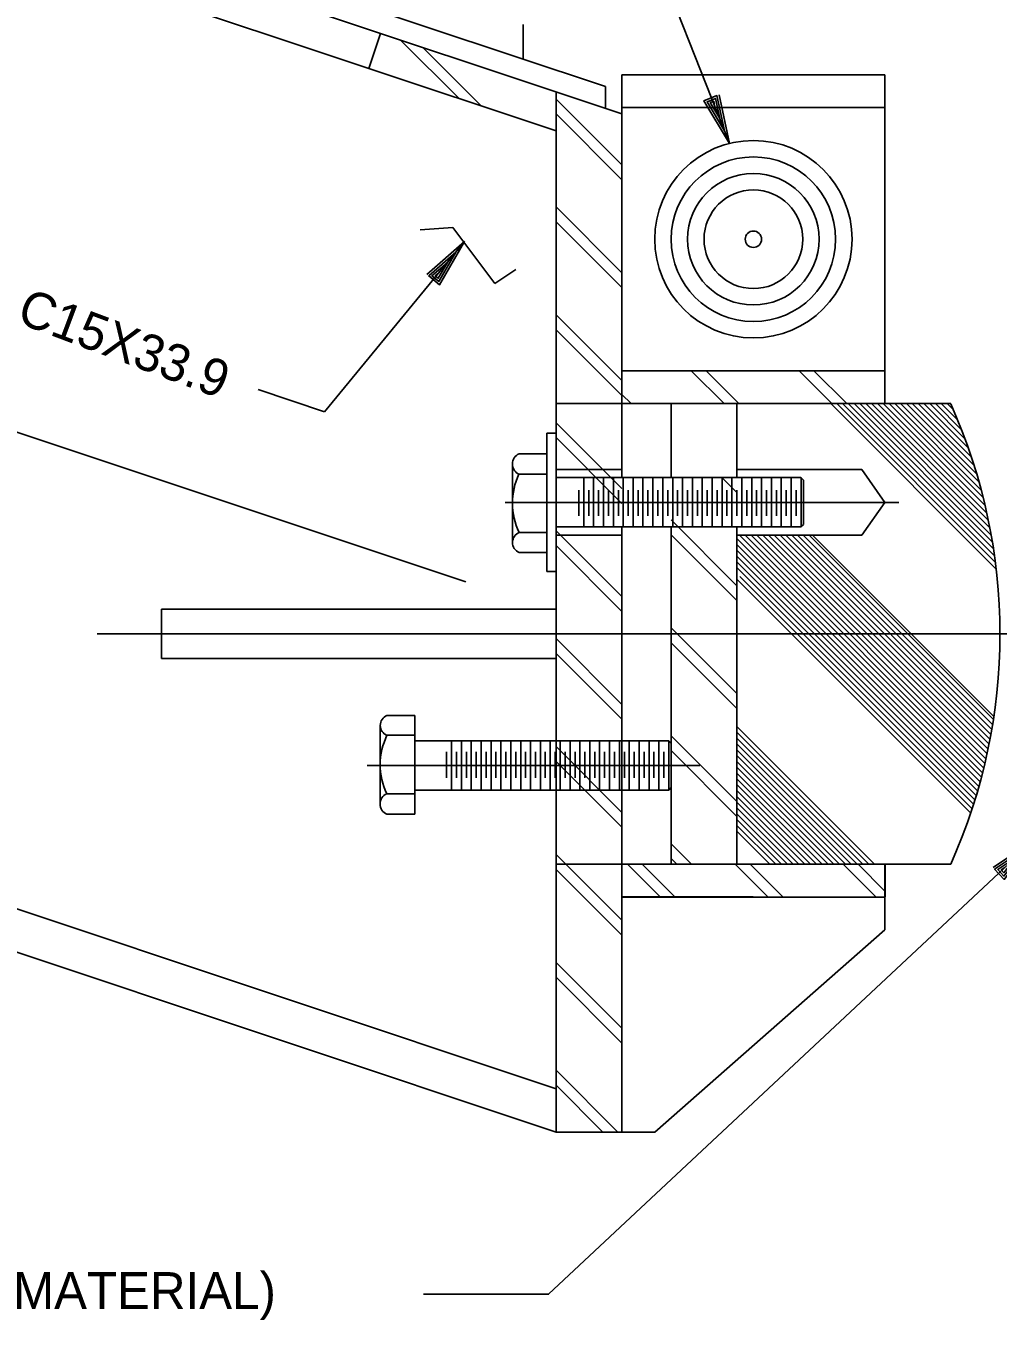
# Model space of a CAD drawing. Extents: x 0.1 to 13.5, y 0.1 to 9.5.
# Drawn here: x 1.9 to 3.132, y 4.936 to 6.576 of the extents above; entities that cross this region are included whole.
import ezdxf

# ---------------------------------------------------------------- set-up
doc = ezdxf.new("R2010")
doc.units = 0
for name, color, linetype in [('Level 1', 7, 'Continuous'), ('Level 13', 7, 'Continuous'), ('Level 25', 7, 'Continuous'), ('Level 3', 7, 'Continuous'), ('Level 44', 7, 'Continuous'), ('Level 50', 7, 'Continuous')]:
    doc.layers.add(name, color=color, linetype=linetype)

msp = doc.modelspace()

# ---------------------------------------------------------------- linework, layer by layer
at = {"layer": 'Level 13'}
for p, q in [((2.5606, 6.0598), (2.5606, 5.8848)), ((2.5606, 6.0598), (2.5722, 6.0598)), ((2.5722, 6.0598), (2.5722, 5.8848)), ((2.5253, 6.0339), (2.5606, 6.0339)), ((2.5606, 6.0339), (2.5606, 5.9089)), ((2.5169, 6.0211), (2.5169, 5.9214)), ((2.525, 6.0081), (2.5606, 6.0081)), ((2.8014, 6.0036), (2.5722, 6.0036)), ((2.6073, 6.0036), (2.6073, 5.9411)), ((2.6198, 6.0036), (2.6198, 5.9411)), ((2.6324, 6.0036), (2.6324, 5.9411)), ((2.6448, 6.0036), (2.6448, 5.9411)), ((2.6574, 6.0036), (2.6574, 5.9411)), ((2.6699, 6.0036), (2.6699, 5.9411)), ((2.6823, 6.0036), (2.6823, 5.9411)), ((2.695, 6.0036), (2.695, 5.9411)), ((2.7074, 6.0036), (2.7074, 5.9411)), ((2.72, 6.0036), (2.72, 5.9411)), ((2.7325, 6.0036), (2.7325, 5.9411)), ((2.7449, 6.0036), (2.7449, 5.9411)), ((2.7575, 6.0036), (2.7575, 5.9411)), ((2.77, 6.0036), (2.77, 5.9411)), ((2.7825, 6.0036), (2.7825, 5.9411)), ((2.795, 6.0036), (2.795, 5.9411)), ((2.8014, 6.0036), (2.8825, 6.0036)), ((2.8075, 6.0036), (2.8075, 5.9411)), ((2.8201, 6.0036), (2.8201, 5.9411)), ((2.8325, 6.0036), (2.8325, 5.9411)), ((2.8451, 6.0036), (2.8451, 5.9411)), ((2.8576, 6.0036), (2.8576, 5.9411)), ((2.87, 6.0036), (2.87, 5.9411)), ((2.8825, 6.0036), (2.8856, 6.0002)), ((2.8826, 6.0036), (2.8826, 5.9411)), ((2.8856, 6.0002), (2.8856, 5.9442)), ((2.601, 5.9879), (2.601, 5.9551)), ((2.6136, 5.9879), (2.6136, 5.9551)), ((2.6261, 5.9879), (2.6261, 5.9551)), ((2.6386, 5.9879), (2.6386, 5.9551)), ((2.6511, 5.9879), (2.6511, 5.9551)), ((2.6636, 5.9879), (2.6636, 5.9551)), ((2.6761, 5.9879), (2.6761, 5.9551)), ((2.6886, 5.9879), (2.6886, 5.9551)), ((2.6886, 5.9879), (2.6886, 5.9551)), ((2.6886, 5.9879), (2.6886, 5.9551)), ((2.6886, 5.9879), (2.6886, 5.9551)), ((2.7012, 5.9879), (2.7012, 5.9551)), ((2.7137, 5.9879), (2.7137, 5.9551)), ((2.7261, 5.9879), (2.7261, 5.9551)), ((2.7387, 5.9879), (2.7387, 5.9551)), ((2.7512, 5.9879), (2.7512, 5.9551)), ((2.7512, 5.9879), (2.7512, 5.9551)), ((2.7512, 5.9879), (2.7512, 5.9551)), ((2.7638, 5.9879), (2.7638, 5.9551)), ((2.7763, 5.9879), (2.7763, 5.9551)), ((2.7887, 5.9879), (2.7887, 5.9551)), ((2.8013, 5.9879), (2.8013, 5.9551)), ((2.8138, 5.9879), (2.8138, 5.9551)), ((2.8138, 5.9879), (2.8138, 5.9551)), ((2.8263, 5.9879), (2.8263, 5.9551)), ((2.8388, 5.9879), (2.8388, 5.9551)), ((2.8513, 5.9879), (2.8513, 5.9551)), ((2.8638, 5.9879), (2.8638, 5.9551)), ((2.8763, 5.9879), (2.8763, 5.9551)), ((2.8014, 5.9411), (2.5722, 5.9411)), ((2.8014, 5.9411), (2.8822, 5.9411)), ((2.8822, 5.9411), (2.8856, 5.9442)), ((2.5252, 5.9341), (2.5606, 5.9341)), ((2.5253, 5.9089), (2.5606, 5.9089)), ((2.5606, 5.8848), (2.5722, 5.8848)), ((2.3493, 5.5902), (2.3493, 5.6899)), ((2.3577, 5.7024), (2.393, 5.7024)), ((2.393, 5.5774), (2.393, 5.7024)), ((2.3576, 5.6772), (2.393, 5.6772)), ((2.6338, 5.6702), (2.393, 5.6702)), ((2.4334, 5.6234), (2.4334, 5.6561)), ((2.4397, 5.6077), (2.4397, 5.6702)), ((2.446, 5.6234), (2.446, 5.6561)), ((2.4522, 5.6077), (2.4522, 5.6702)), ((2.4585, 5.6234), (2.4585, 5.6561)), ((2.4648, 5.6077), (2.4648, 5.6702)), ((2.471, 5.6234), (2.471, 5.6561)), ((2.4772, 5.6077), (2.4772, 5.6702)), ((2.4835, 5.6234), (2.4835, 5.6561)), ((2.4898, 5.6077), (2.4898, 5.6702)), ((2.496, 5.6234), (2.496, 5.6561)), ((2.5023, 5.6077), (2.5023, 5.6702)), ((2.5085, 5.6234), (2.5085, 5.6561)), ((2.5147, 5.6077), (2.5147, 5.6702)), ((2.521, 5.6234), (2.521, 5.6561)), ((2.521, 5.6234), (2.521, 5.6561)), ((2.521, 5.6234), (2.521, 5.6561)), ((2.521, 5.6234), (2.521, 5.6561)), ((2.5274, 5.6077), (2.5274, 5.6702)), ((2.5336, 5.6234), (2.5336, 5.6561)), ((2.5398, 5.6077), (2.5398, 5.6702)), ((2.5461, 5.6234), (2.5461, 5.6561)), ((2.5524, 5.6077), (2.5524, 5.6702)), ((2.5585, 5.6234), (2.5585, 5.6561)), ((2.5649, 5.6077), (2.5649, 5.6702)), ((2.5711, 5.6234), (2.5711, 5.6561)), ((2.5773, 5.6077), (2.5773, 5.6702)), ((2.5836, 5.6234), (2.5836, 5.6561)), ((2.5836, 5.6234), (2.5836, 5.6561)), ((2.5836, 5.6234), (2.5836, 5.6561)), ((2.5899, 5.6077), (2.5899, 5.6702)), ((2.5962, 5.6234), (2.5962, 5.6561)), ((2.6024, 5.6077), (2.6024, 5.6702)), ((2.6087, 5.6234), (2.6087, 5.6561)), ((2.6149, 5.6077), (2.6149, 5.6702)), ((2.6211, 5.6234), (2.6211, 5.6561)), ((2.6274, 5.6077), (2.6274, 5.6702)), ((2.6337, 5.6234), (2.6337, 5.6561)), ((2.6338, 5.6702), (2.7146, 5.6702)), ((2.6399, 5.6077), (2.6399, 5.6702)), ((2.6462, 5.6234), (2.6462, 5.6561)), ((2.6462, 5.6234), (2.6462, 5.6561)), ((2.6525, 5.6077), (2.6525, 5.6702)), ((2.6587, 5.6234), (2.6587, 5.6561)), ((2.6649, 5.6077), (2.6649, 5.6702)), ((2.6712, 5.6234), (2.6712, 5.6561)), ((2.6775, 5.6077), (2.6775, 5.6702)), ((2.6837, 5.6234), (2.6837, 5.6561)), ((2.69, 5.6077), (2.69, 5.6702)), ((2.6962, 5.6234), (2.6962, 5.6561)), ((2.7024, 5.6077), (2.7024, 5.6702)), ((2.7087, 5.6234), (2.7087, 5.6561)), ((2.7146, 5.6702), (2.718, 5.6671)), ((2.715, 5.6077), (2.715, 5.6702)), ((2.718, 5.611), (2.718, 5.6671)), ((2.6338, 5.6077), (2.393, 5.6077)), ((2.6338, 5.6077), (2.7149, 5.6077)), ((2.7149, 5.6077), (2.718, 5.611)), ((2.3574, 5.6032), (2.393, 5.6032)), ((2.3577, 5.5774), (2.393, 5.5774))]:
    msp.add_line(p, q, dxfattribs=at)
for centre, radius, start, end in [((2.5309, 6.0209), 0.0141, 113.1675, 245.9991), ((2.6023, 5.9714), 0.0854, 154.5519, 205.884), ((2.5307, 5.9215), 0.0137, 112.375, 247.1995), ((2.3631, 5.6898), 0.0137, 112.8005, 247.625), ((2.4347, 5.6399), 0.0854, 154.116, 205.4481), ((2.3633, 5.5903), 0.0141, 114.0009, 246.8325)]:
    msp.add_arc(centre, radius, start, end, dxfattribs=at)
at = {"layer": 'Level 25'}
for p, q in [((2.4512, 7.2856), (2.7921, 6.4269)), ((1.3561, 6.9251), (2.6347, 6.4989)), ((1.3478, 6.9003), (2.6555, 6.4644)), ((1.333, 6.8559), (2.5722, 6.4428)), ((2.5305, 6.5336), (2.5305, 6.5775)), ((2.3499, 6.5663), (2.335, 6.5219)), ((2.9889, 6.514), (2.6555, 6.514)), ((2.6555, 6.0036), (2.6555, 6.514)), ((2.9889, 6.0973), (2.9889, 6.514)), ((2.5722, 5.1746), (2.5722, 6.4922)), ((2.6347, 6.4714), (2.6347, 6.4989)), ((2.9889, 6.4723), (2.6555, 6.4723)), ((2.3999, 6.3174), (2.4413, 6.3203)), ((2.4413, 6.3203), (2.4946, 6.2493)), ((1.1502, 6.3074), (2.4579, 5.8715)), ((2.2788, 6.0871), (2.4561, 6.3026)), ((2.4946, 6.2493), (2.5212, 6.2671)), ((2.9889, 6.139), (2.6555, 6.139)), ((2.1945, 6.1152), (2.2788, 6.0871)), ((2.6555, 6.0973), (2.5722, 6.0973)), ((3.0722, 6.0973), (2.6555, 6.0973)), ((2.718, 6.0036), (2.718, 6.0973)), ((2.8014, 6.0036), (2.8014, 6.0973)), ((2.6555, 6.014), (2.5722, 6.014)), ((2.9597, 6.014), (2.8014, 6.014)), ((2.9597, 6.014), (2.9889, 5.9723)), ((3.0067, 5.9723), (2.5078, 5.9723)), ((2.9597, 5.9306), (2.9889, 5.9723)), ((2.6555, 5.1746), (2.6555, 5.9411)), ((2.718, 5.514), (2.718, 5.9411)), ((2.8014, 5.514), (2.8014, 5.9411)), ((2.6555, 5.9306), (2.5722, 5.9306)), ((2.9597, 5.9306), (2.8014, 5.9306)), ((2.5722, 5.8369), (2.0722, 5.8369)), ((2.0722, 5.7744), (2.0722, 5.8369)), ((3.2313, 5.8056), (1.9905, 5.8056)), ((3.2313, 5.8056), (1.9905, 5.8056)), ((3.0381, 5.8056), (3.6139, 5.8056)), ((3.0381, 5.8056), (4.2789, 5.8056)), ((2.5722, 5.7744), (2.0722, 5.7744)), ((0.969, 5.7639), (2.5722, 5.2295)), ((0.9526, 5.7145), (2.5722, 5.1746)), ((2.7544, 5.639), (2.3328, 5.639)), ((2.6555, 5.514), (2.5722, 5.514)), ((3.0722, 5.514), (2.6555, 5.514)), ((2.9889, 5.4306), (2.9889, 5.514)), ((2.9889, 5.4306), (2.989, 5.514)), ((2.9889, 5.4723), (2.6555, 5.4723)), ((2.9889, 5.4723), (2.6556, 5.4729)), ((2.6972, 5.1745), (2.9889, 5.4306)), ((2.5722, 5.1746), (2.6555, 5.1746)), ((2.6972, 5.1745), (2.6555, 5.1746))]:
    msp.add_line(p, q, dxfattribs=at)
for radius in [0.125, 0.1042, 0.0833, 0.0625, 0.0104]:
    msp.add_circle((2.8222, 6.3056), radius, dxfattribs=at)
msp.add_arc((2.4229, 5.8056), 0.7118, 335.8105, 24.1895, dxfattribs=at)
at = {"layer": 'Level 3'}
for p, q in [((3.13, 5.8877), (2.9204, 6.0973)), ((3.1289, 5.8961), (2.9278, 6.0973)), ((3.1278, 5.9046), (2.9351, 6.0973)), ((3.1265, 5.9133), (2.9425, 6.0973)), ((3.1251, 5.922), (2.9499, 6.0973)), ((3.1236, 5.9309), (2.9572, 6.0973)), ((3.1219, 5.94), (2.9646, 6.0973)), ((3.1201, 5.9492), (2.9719, 6.0973)), ((3.1181, 5.9585), (2.9793, 6.0973)), ((3.1159, 5.9681), (2.9867, 6.0973)), ((3.1136, 5.9778), (2.9941, 6.0973)), ((3.111, 5.9877), (3.0014, 6.0973)), ((3.1083, 5.9978), (3.0088, 6.0973)), ((3.1053, 6.0082), (3.0162, 6.0973)), ((3.1021, 6.0188), (3.0235, 6.0973)), ((3.0985, 6.0296), (3.0309, 6.0973)), ((3.0947, 6.0408), (3.0382, 6.0973)), ((3.0906, 6.0523), (3.0456, 6.0973)), ((3.0861, 6.0642), (3.053, 6.0973)), ((3.0812, 6.0765), (3.0603, 6.0973)), ((3.0758, 6.0893), (3.0677, 6.0973)), ((3.1096, 5.6182), (2.8014, 5.9264)), ((3.108, 5.6124), (2.8014, 5.919)), ((3.1111, 5.624), (2.8045, 5.9306)), ((3.1127, 5.6298), (2.8119, 5.9306)), ((3.1141, 5.6357), (2.8192, 5.9306)), ((3.1156, 5.6417), (2.8266, 5.9306)), ((3.1169, 5.6476), (2.834, 5.9306)), ((3.1183, 5.6537), (2.8413, 5.9306)), ((3.1196, 5.6597), (2.8487, 5.9306)), ((3.1208, 5.6659), (2.8561, 5.9306)), ((3.1221, 5.672), (2.8634, 5.9306)), ((3.1232, 5.6782), (2.8708, 5.9306)), ((3.1243, 5.6845), (2.8781, 5.9306)), ((3.1254, 5.6908), (2.8855, 5.9306)), ((3.1264, 5.6971), (2.8929, 5.9306)), ((3.127, 5.7009), (2.8972, 5.9306)), ((3.1063, 5.6067), (2.8014, 5.9117)), ((3.1047, 5.601), (2.8014, 5.9043)), ((3.1029, 5.5954), (2.8014, 5.8969)), ((3.1012, 5.5898), (2.8014, 5.8896)), ((3.0976, 5.5787), (2.8014, 5.8748)), ((3.0994, 5.5842), (2.8051, 5.8785)), ((2.9757, 5.514), (2.8014, 5.6883)), ((2.9684, 5.514), (2.8014, 5.681)), ((2.961, 5.514), (2.8014, 5.6736)), ((2.9536, 5.514), (2.8014, 5.6662)), ((2.9463, 5.514), (2.8014, 5.6589)), ((2.9389, 5.514), (2.8014, 5.6515)), ((2.9315, 5.514), (2.8014, 5.6441)), ((2.9242, 5.514), (2.8014, 5.6368)), ((2.9168, 5.514), (2.8014, 5.6294)), ((2.9095, 5.514), (2.8014, 5.6221)), ((2.9021, 5.514), (2.8014, 5.6147)), ((2.8947, 5.514), (2.8014, 5.6073)), ((2.8874, 5.514), (2.8014, 5.5999)), ((2.88, 5.514), (2.8014, 5.5926)), ((2.8726, 5.514), (2.8014, 5.5852)), ((2.8653, 5.514), (2.8014, 5.5778)), ((2.8579, 5.514), (2.8014, 5.5705)), ((2.8505, 5.514), (2.8014, 5.5631)), ((2.8432, 5.514), (2.8014, 5.5558))]:
    msp.add_line(p, q, dxfattribs=at)
for points in [[(2.4044, 4.9691), (2.5626, 4.9691), (3.1785, 5.5448)], [(3.1259, 5.5098), (3.1785, 5.5448), (3.14, 5.4947), (3.1279, 5.5076), (3.1658, 5.5329), (3.1397, 5.4989), (3.1319, 5.5072), (3.1536, 5.5216), (3.1394, 5.5032), (3.1362, 5.5066), (3.141, 5.5097)]]:
    msp.add_lwpolyline(points, dxfattribs=at)
at = {"layer": 'Level 44'}
for p, q in [((2.4493, 6.4838), (2.3752, 6.5579)), ((2.4776, 6.4743), (2.4035, 6.5484)), ((2.6555, 6.3999), (2.5722, 6.4832)), ((2.6555, 6.381), (2.5722, 6.4644)), ((2.6555, 6.2632), (2.5722, 6.3465)), ((2.6555, 6.2443), (2.5722, 6.3277)), ((2.6555, 6.1265), (2.5722, 6.2098)), ((2.6555, 6.1076), (2.5722, 6.191)), ((2.785, 6.0973), (2.7434, 6.139)), ((2.8039, 6.0973), (2.7622, 6.139)), ((2.9217, 6.0973), (2.8801, 6.139)), ((2.9406, 6.0973), (2.8989, 6.139)), ((2.6672, 6.0973), (2.6555, 6.1089)), ((2.6555, 5.9898), (2.5722, 6.0731)), ((2.6555, 5.9709), (2.5722, 6.0543)), ((2.8014, 5.9846), (2.7824, 6.0036)), ((2.8014, 6.0034), (2.8012, 6.0036)), ((2.6555, 5.8531), (2.5722, 5.9364)), ((2.8014, 5.8667), (2.718, 5.95)), ((2.8014, 5.8478), (2.718, 5.9312)), ((2.6555, 5.8342), (2.5722, 5.9175)), ((2.8014, 5.73), (2.718, 5.8133)), ((2.6555, 5.7164), (2.5722, 5.7997)), ((2.8014, 5.7111), (2.718, 5.7945)), ((2.6555, 5.6975), (2.5722, 5.7808)), ((2.8014, 5.5933), (2.718, 5.6766)), ((2.6555, 5.5796), (2.5722, 5.663)), ((2.8014, 5.5744), (2.718, 5.6578)), ((2.6555, 5.5608), (2.5722, 5.6441)), ((2.6555, 5.4429), (2.5722, 5.5263)), ((2.744, 5.514), (2.718, 5.5399)), ((2.7043, 5.4723), (2.6626, 5.514)), ((2.7231, 5.4723), (2.6814, 5.514)), ((2.7251, 5.514), (2.718, 5.5211)), ((2.841, 5.4723), (2.7993, 5.514)), ((2.8598, 5.4723), (2.8181, 5.514)), ((2.9777, 5.4723), (2.936, 5.514)), ((2.9889, 5.4799), (2.9549, 5.514)), ((2.6555, 5.4241), (2.5722, 5.5074)), ((2.6555, 5.3062), (2.5722, 5.3896)), ((2.6555, 5.2874), (2.5722, 5.3707)), ((2.6505, 5.1746), (2.5722, 5.2529)), ((2.6316, 5.1746), (2.5722, 5.234))]:
    msp.add_line(p, q, dxfattribs=at)
at = {"layer": 'Level 50'}
for p, q in [((2.7857, 6.4431), (2.7857, 6.4431)), ((2.7921, 6.4269), (2.7921, 6.4269)), ((2.4561, 6.3026), (2.4561, 6.3026)), ((2.4451, 6.2892), (2.4451, 6.2892))]:
    msp.add_line(p, q, dxfattribs=at)
for points in [[(2.7787, 6.4887), (2.7921, 6.4269), (2.7595, 6.4811), (2.7759, 6.4876), (2.7857, 6.4431), (2.7635, 6.4798), (2.7741, 6.484), (2.7795, 6.4586), (2.7676, 6.4786), (2.772, 6.4803), (2.7731, 6.4747)], [(2.4086, 6.261), (2.4561, 6.3026), (2.4245, 6.2479), (2.4109, 6.2591), (2.4451, 6.2892), (2.4236, 6.2521), (2.4149, 6.2593), (2.4345, 6.2763), (2.4228, 6.2562), (2.4191, 6.2592), (2.4235, 6.2629)]]:
    msp.add_lwpolyline(points, dxfattribs=at)

# ---------------------------------------------------------------- texts
at = {"layer": 'Level 1'}
msp.add_text('C15X33.9', height=0.0467, rotation=339.4353, dxfattribs=at).set_placement((1.8868, 6.2008))
msp.add_text('(MOLDED RUBBER OR APPROVED MATERIAL)', height=0.046698, dxfattribs=at).set_placement((0.8258, 4.9505))

doc.saveas('drawing.dxf')
